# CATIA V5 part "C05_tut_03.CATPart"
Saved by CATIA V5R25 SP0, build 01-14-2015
Part number: Part1
Bounding box of the stored display mesh (mm): x -75 to 75, y -150 to 150, z 0 to 150
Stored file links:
  E:\ashutosh\Academics\Catia\CATIA V5-6R2013_partfiles\Tutorials_ver_2\C05_tut_03.CATPart
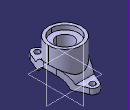
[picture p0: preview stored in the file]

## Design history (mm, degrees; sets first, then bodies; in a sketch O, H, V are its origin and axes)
Body1 (main body)
  Sketch1 on yz-plane, origin (0, 0, 0), H (0, 1, 0), V (0, 0, 1)
    point P1 (-150, 0)
    line L1 (-150, 0) -> (-74.162, 0)
    line L2 (150, 0) -> (150, 25)
    line L3 (150, 25) -> (89.4427, 25)
    line L4 (-150, 25) -> (-150, 0)
    point P2 (150, 0)
    arc A1 centre (0, -30) radius 80 from (74.162, 0) to (-74.162, 0) ccw
    point P5 (0, -30)
    arc A2 centre (0, -30) radius 105 from (89.4427, 25) to (-89.4427, 25) ccw
    line L5 (74.162, 0) -> (150, 0)
    line L6 (-89.4427, 25) -> (-150, 25)
    length L2 = 25
    distance V L4 = 150
    distance L1 P5 = 30
    radius A1 = 80
    radius A2 = 105
    distance P1 P2 = 300
    coincidence: P1 H, P5 V, L1 L5, L3 L6
    horizontal: L1 H, L3 H, L5 H, L6 H
    vertical: L2 V, L4 V
  Pad1: profile Sketch1, direction (1, 0, 0), length 75, mirrored extent
  Sketch2 on xy-plane, origin (0, 0, 0), H (1, 0, 0), V (0, 1, 0)
    arc A1 centre (0, 0) radius 75 from (-68.7386, 30) to (-68.7386, -30) ccw
    arc A2 centre (0, 125) radius 25 from (22.9129, 135) to (-22.9129, 135) ccw
    point P1 (0, 125)
    reference intersected line E1 through (0, 0) direction (-1, 0) from zx-plane
    point P4 (0, -125)
    arc A3 centre (0, -125) radius 25 from (22.9129, -135) to (-22.9129, -135) cw
    line L1 (-22.9129, 135) -> (-68.7386, 30)
    line L2 (22.9129, 135) -> (68.7386, 30)
    line L3 (-68.7386, -30) -> (-22.9129, -135)
    line L4 (22.9129, -135) -> (68.7386, -30)
    point P12 (68.7386, -30)
    arc A4 centre (0, 0) radius 75 from (68.7386, -30) to (68.7386, 30) ccw
    radius A1 = 75
    distance P1 P4 = 250
    radius A2 = 25
    coincidence: P1 V, A1 P12, A1 A4
    symmetry: A2 A3 E1
    tangency: L1 A2, L1 A1, L2 A2, L2 A1, L3 A1, L3 A3, L4 A3, L4 A1
  Pocket1: profile Sketch2, direction (0, 0, -1), length 83, mirrored extent, outer side
  Plane1: type Offset, RefPlane xy-plane, Offset 150
  Sketch3 on Plane1, origin (0, 0, 150), H (1, 0, 0), V (0, 1, 0)
    circle A1 centre (0, 0) radius 75
    radius A1 = 75
  Pad2: profile Sketch3, direction (0, 0, 1), up to face of Pad1 from Sketch1.A2
  Sketch4 on yz-plane, origin (0, 0, 0), H (0, 1, 0), V (0, 0, 1)
    point P1 (0, 150)
    line L1 (0, 150) -> (0, 0)
    line L2 (0, 0) -> (37.5, 0)
    line L3 (37.5, 0) -> (37.5, 130)
    line L4 (37.5, 130) -> (61.5, 130)
    line L5 (61.5, 130) -> (61.5, 150)
    line L6 (61.5, 150) -> (0, 150)
    reference projected line E1 (-75, 150) -> (75, 150) from edge [face of Pad2 from Sketch3.A1 | start face of Pad2]
    axis line L7 (0, 209.2639) -> (0, 0)
    point P7 (0, 209.2639)
    length L5 = 20
    radius about axis L5 L7 = 61.5
    radius about axis L7 L3 = 37.5
    coincidence: P1 V, L6 E1, P7 V, L2 H
    vertical: L1 V, L5 V, L3 V, L7 V
    horizontal: L2 H, L4 H, L6 H
  Groove1: profile Sketch4, axis Sketch4.L7, angle 360
  Sketch5 on xy-plane, origin (0, 0, 0), H (1, 0, 0), V (0, 1, 0)
    circle A1 centre (0, 125) radius 12.5
    point P1 (0, 125)
    reference intersected line E1 through (0, 0) direction (-1, 0) from zx-plane
    point P4 (0, -125)
    circle A2 centre (0, -125) radius 12.5
    distance P1 P4 = 250
    radius A1 = 12.5
    coincidence: P1 V
    symmetry: A1 A2 E1
  Pocket2: profile Sketch5, direction (0, 0, -1), through (limit type 3)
